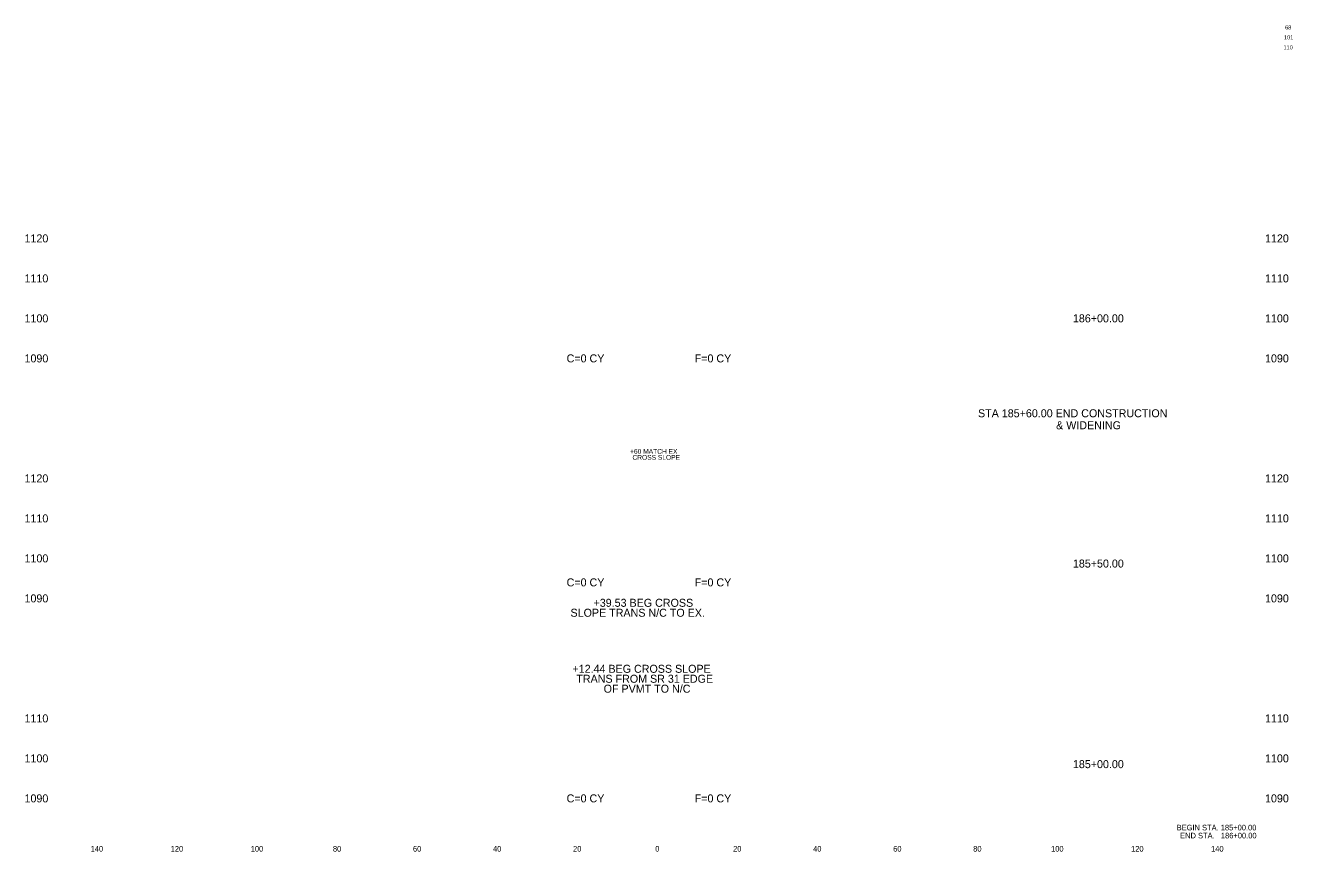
# Model space of a CAD drawing. Extents: x 1002 to 1319, y 998 to 1204.
import ezdxf

# ---------------------------------------------------------------- set-up
doc = ezdxf.new("R2010")
doc.units = 0
for name, color, linetype in [('Default', 7, 'Continuous'), ('DESIGN - SHEET - Corner Text', 7, 'Continuous'), ('DESIGN - TYPICAL - Finished Grade Slopes Text', 7, 'Continuous'), ('DESIGN - TYPICAL - Text', 7, 'Continuous')]:
    doc.layers.add(name, color=color, linetype=linetype)

msp = doc.modelspace()

# ---------------------------------------------------------------- texts
at = {"layer": 'Default'}
for s, height, p in [('     1120     ', 2, (998.01, 1150)), ('     1120     ', 2, (1308.01, 1150)), ('     1110     ', 2, (998.01, 1140)), ('     1110     ', 2, (1308.01, 1140)), ('     1100     ', 2, (998.01, 1130)), ('     186+00.00     ', 2, (1260, 1130.01)), ('     1100     ', 2, (1308.01, 1130)), ('     1090     ', 2, (998.01, 1120)), ('     1090     ', 2, (1308.01, 1120)), ('     1120     ', 2, (998.01, 1090)), ('     1120     ', 2, (1308.01, 1090)), ('     1110     ', 2, (998.01, 1080)), ('     1110     ', 2, (1308.01, 1080)), ('     1100     ', 2, (998.01, 1070)), ('     185+50.00     ', 2, (1260, 1068.71)), ('     1100     ', 2, (1308.01, 1070)), ('     1090     ', 2, (998.01, 1060)), ('     1090     ', 2, (1308.01, 1060)), ('     1110     ', 2, (998.01, 1030)), ('     1110     ', 2, (1308.01, 1030)), ('     1100     ', 2, (998.01, 1020)), ('     185+00.00     ', 2, (1260, 1018.56)), ('     1100     ', 2, (1308.01, 1020)), ('     1090     ', 2, (998.01, 1010)), ('     1090     ', 2, (1308.01, 1010)), ('     140     ', 1.4, (1015.65, 997.7)), ('     120     ', 1.4, (1035.65, 997.7)), ('     100     ', 1.4, (1055.65, 997.7)), ('     80     ', 1.4, (1076.2, 997.7)), ('     60     ', 1.4, (1096.2, 997.7)), ('     40     ', 1.4, (1116.2, 997.7)), ('     20     ', 1.4, (1136.2, 997.7)), ('     0     ', 1.4, (1156.74, 997.7)), ('     0     ', 1.4, (1156.74, 997.7)), ('     20     ', 1.4, (1176.2, 997.7)), ('     40     ', 1.4, (1196.2, 997.7)), ('     60     ', 1.4, (1216.2, 997.7)), ('     80     ', 1.4, (1236.2, 997.7)), ('     100     ', 1.4, (1255.65, 997.7)), ('     120     ', 1.4, (1275.65, 997.7)), ('     140     ', 1.4, (1295.65, 997.7))]:
    msp.add_text(s, height=height, dxfattribs=at).set_placement(p)
at = {"layer": 'DESIGN - SHEET - Corner Text'}
for s, height, p in [('68', 1, (1316.75, 1203.25)), ('101', 1, (1316.46, 1200.75)), ('110', 1, (1316.35, 1198.26)), ('BEGIN STA. 185+00.00', 1.4, (1289.64, 1003)), ('END STA.   186+00.00', 1.4, (1290.51, 1001))]:
    msp.add_text(s, height=height, dxfattribs=at).set_placement(p)
at = {"layer": 'DESIGN - TYPICAL - Finished Grade Slopes Text'}
for s, height, p in [('+60 MATCH EX', 1.2, (1153.06, 1097.15)), ('CROSS SLOPE', 1.2, (1153.65, 1095.65)), ('SLOPE TRANS N/C TO EX.', 2, (1138.17, 1056.41)), ('+39.53 BEG CROSS ', 2, (1143.92, 1058.9)), ('+12.44 BEG CROSS SLOPE', 2, (1138.65, 1042.4)), ('TRANS FROM SR 31 EDGE', 2, (1139.62, 1039.91)), ('OF PVMT TO N/C ', 2, (1146.45, 1037.42))]:
    msp.add_text(s, height=height, dxfattribs=at).set_placement(p)
at = {"layer": 'DESIGN - TYPICAL - Text'}
for s, p in [('C=0 CY', (1137.2, 1120)), ('F=0 CY', (1169.2, 1120)), ('STA 185+60.00 END CONSTRUCTION ', (1240, 1106.28)), ('& WIDENING', (1259.52, 1103.28)), ('C=0 CY', (1137.2, 1064)), ('F=0 CY', (1169.2, 1064)), ('C=0 CY', (1137.2, 1010)), ('F=0 CY', (1169.2, 1010))]:
    msp.add_text(s, height=2, dxfattribs=at).set_placement(p)

doc.saveas('drawing.dxf')
